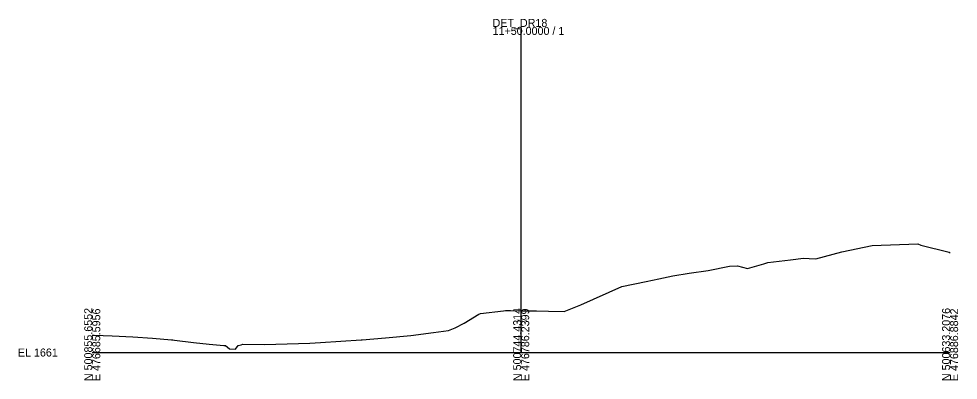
# Model space of a CAD drawing. Extents: x -26 to 303, y -10 to 3627.
# Drawn here: x -25.7 to 302.8, y 2990.3 to 3116.8 of the extents above; entities that cross this region are included whole.
import ezdxf

# ---------------------------------------------------------------- set-up
doc = ezdxf.new("R2010")
doc.units = 0
for name, color, linetype in [('Exist Cross Section Cell', 7, 'Continuous'), ('Exist XS Center Line Elevation Label', 7, 'Continuous'), ('Exist XS Ground Line', 7, 'Continuous')]:
    doc.layers.add(name, color=color, linetype=linetype)

msp = doc.modelspace()

# ---------------------------------------------------------------- linework, layer by layer
at = {"layer": 'Exist Cross Section Cell'}
for p, q in [((150, 3000), (150, 3113.94)), ((0, 3000), (150, 3000)), ((150, 3000), (300, 3000))]:
    msp.add_line(p, q, dxfattribs=at)
at = {"layer": 'Exist XS Ground Line'}
msp.add_lwpolyline([(0, 3006.12), (0.69, 3006.1), (6.94, 3005.85), (14.18, 3005.5), (21.1, 3005.04), (27.67, 3004.48), (28.18, 3004.44), (28.75, 3004.37), (35.36, 3003.52), (40.94, 3002.97), (45.97, 3002.47), (46.63, 3002.42), (47.99, 3001.27), (50.15, 3001.2), (50.98, 3002.45), (52.04, 3002.74), (52.65, 3002.9), (60.18, 3002.75), (76.04, 3003.31), (79.79, 3003.48), (94.02, 3004.42), (94.36, 3004.44), (102.59, 3005.12), (111.36, 3005.94), (119.36, 3007.02), (124.64, 3007.67), (126.94, 3008.65), (130.08, 3010.24), (135.25, 3013.39), (135.74, 3013.68), (143.87, 3014.58), (144.49, 3014.65), (146.27, 3014.65), (150, 3014.64), (155.34, 3014.61), (159.54, 3014.52), (165.09, 3014.39), (170.89, 3016.64), (185.17, 3023.15), (193.7, 3024.82), (198.13, 3025.75), (203.03, 3026.79), (208.76, 3027.81), (215.43, 3028.7), (222.9, 3030.21), (225.62, 3030.28), (229.13, 3029.42), (234.92, 3031.07), (235.51, 3031.29), (236.28, 3031.46), (244.19, 3032.43), (248.69, 3032.98), (250.7, 3032.89), (253, 3032.82), (262.13, 3035.18), (272.79, 3037.47), (288.75, 3037.98), (289.81, 3037.53), (299.64, 3035.11), (300, 3034.94)], dxfattribs=at)

# ---------------------------------------------------------------- texts
at = {"layer": 'Exist Cross Section Cell'}
for s, p in [('DET_DR18', (140, 3113.94)), ('11+50.0000 / 1', (140, 3111.14)), ('EL 1661', (-26, 2998.6))]:
    msp.add_text(s, height=2.8, dxfattribs=at).set_placement(p)
for s, p in [('N 500855.6552', (0, 2990)), ('E 476685.5956', (2.8, 2990)), ('N 500744.4314', (150, 2990)), ('E 476786.2399', (152.8, 2990)), ('N 500633.2076', (300, 2990)), ('E 476886.8842', (302.8, 2990))]:
    msp.add_text(s, height=2.8, rotation=90, dxfattribs=at).set_placement(p)
at = {"layer": 'Exist XS Center Line Elevation Label'}
msp.add_text('1675.64', height=0.75, dxfattribs=at).set_placement((148.29, 3010.89))

doc.saveas('drawing.dxf')
